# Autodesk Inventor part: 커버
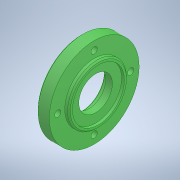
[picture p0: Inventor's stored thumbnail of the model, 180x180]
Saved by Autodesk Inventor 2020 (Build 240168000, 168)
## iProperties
Created: 2024-04
Part Number: 커버
Material: 알루미늄 6061
Document SubType Name: Modeling
Designer: oem
Density: 2.71 g/cm^3
Appearance: 기본값
Author: jhkim
Sending System: Autodesk Inventor 2025
Preprocessor: ST-DEVELOPER v20
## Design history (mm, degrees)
feature "솔리드1"
node "솔리드2"
